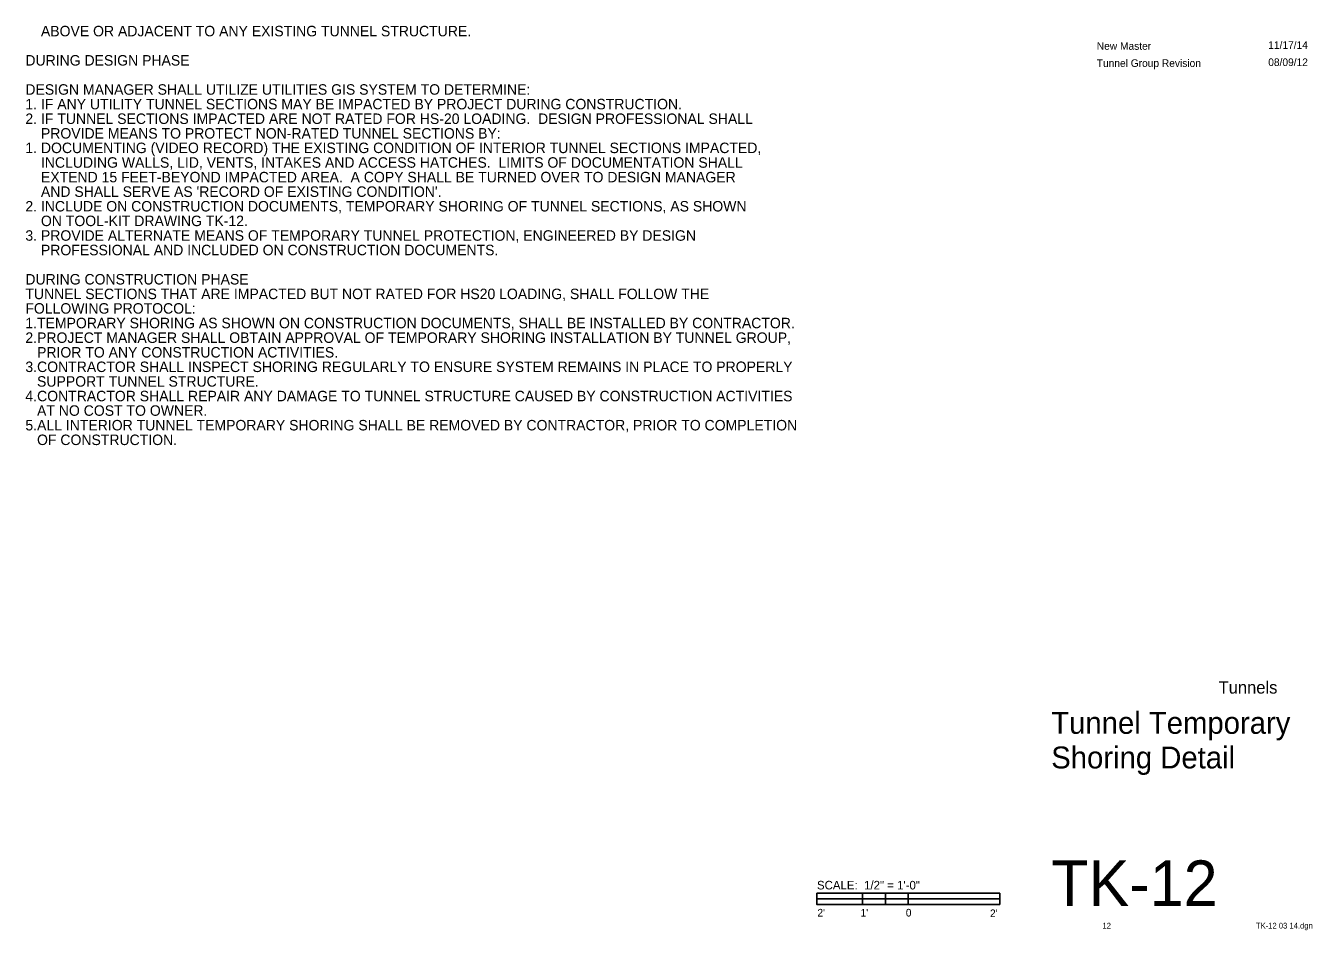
# Model space of a CAD drawing. Extents: x 10051 to 10282, y 10006 to 10178.
# Drawn here: x 10169.7 to 10282.4, y 10005.7 to 10084.8 of the extents above; entities that cross this region are included whole.
import ezdxf

# ---------------------------------------------------------------- set-up
doc = ezdxf.new("R2010")
doc.units = 0
for name, color, linetype in [('G-ANNO-CELL', 7, 'Continuous'), ('G-ANNO-TEXT', 7, 'Continuous'), ('G-DETL-LINE', 7, 'Continuous'), ('G-TITL-TEXT', 7, 'Continuous')]:
    doc.layers.add(name, color=color, linetype=linetype)

msp = doc.modelspace()

# ---------------------------------------------------------------- linework, layer by layer
at = {"layer": 'G-ANNO-CELL'}
for p, q in [((10238.99, 10008.91), (10246.99, 10008.91)), ((10238.99, 10008.91), (10238.99, 10007.91)), ((10242.99, 10008.91), (10242.99, 10007.91)), ((10246.99, 10008.91), (10254.99, 10008.91)), ((10246.99, 10008.91), (10246.99, 10007.91)), ((10254.99, 10008.91), (10254.99, 10007.91)), ((10238.99, 10008.41), (10242.99, 10008.41)), ((10238.99, 10007.91), (10246.99, 10007.91)), ((10242.99, 10008.41), (10246.99, 10008.41)), ((10246.99, 10008.41), (10254.99, 10008.41)), ((10246.99, 10007.91), (10254.99, 10007.91))]:
    msp.add_line(p, q, dxfattribs=at)
for points in [[(10242.99, 10008.41), (10244.99, 10008.41), (10244.99, 10008.91), (10242.99, 10008.91)], [(10246.99, 10008.91), (10254.99, 10008.91), (10254.99, 10008.41), (10246.99, 10008.41)], [(10238.99, 10008.41), (10242.99, 10008.41), (10242.99, 10007.91), (10238.99, 10007.91)], [(10244.99, 10007.91), (10246.99, 10007.91), (10246.99, 10008.41), (10244.99, 10008.41)]]:
    msp.add_lwpolyline(points, close=True, dxfattribs=at)

# ---------------------------------------------------------------- texts
for s, height, p in [('SCALE:  1/2" = 1\'-0"', 0.75, (10238.99, 10009.24)), ("2'", 0.667, (10239.03, 10006.87)), ("1'", 0.667, (10242.81, 10006.87)), ('0', 0.667, (10246.77, 10006.87)), ("2'", 0.667, (10254.14, 10006.82))]:
    msp.add_text(s, height=height, dxfattribs=at).set_placement(p)
at = {"layer": 'G-ANNO-TEXT'}
for s, p in [('    ABOVE OR ADJACENT TO ANY EXISTING TUNNEL STRUCTURE. ', (10169.69, 10083.9)), ('DURING DESIGN PHASE', (10169.69, 10081.34)), ('DESIGN MANAGER SHALL UTILIZE UTILITIES GIS SYSTEM TO DETERMINE:', (10169.69, 10078.79)), ('1. IF ANY UTILITY TUNNEL SECTIONS MAY BE IMPACTED BY PROJECT DURING CONSTRUCTION.', (10169.69, 10077.51)), ('2. IF TUNNEL SECTIONS IMPACTED ARE NOT RATED FOR HS-20 LOADING.  DESIGN PROFESSIONAL SHALL ', (10169.69, 10076.23)), ('    PROVIDE MEANS TO PROTECT NON-RATED TUNNEL SECTIONS BY:', (10169.69, 10074.95)), ('1. DOCUMENTING (VIDEO RECORD) THE EXISTING CONDITION OF INTERIOR TUNNEL SECTIONS IMPACTED, ', (10169.69, 10073.68)), ('    INCLUDING WALLS, LID, VENTS, INTAKES AND ACCESS HATCHES.  LIMITS OF DOCUMENTATION SHALL ', (10169.69, 10072.4)), ('    EXTEND 15 FEET-BEYOND IMPACTED AREA.  A COPY SHALL BE TURNED OVER TO DESIGN MANAGER ', (10169.69, 10071.12)), ("    AND SHALL SERVE AS 'RECORD OF EXISTING CONDITION'.", (10169.69, 10069.85)), ('2. INCLUDE ON CONSTRUCTION DOCUMENTS, TEMPORARY SHORING OF TUNNEL SECTIONS, AS SHOWN ', (10169.69, 10068.57)), ('    ON TOOL-KIT DRAWING TK-12.', (10169.69, 10067.29)), ('3. PROVIDE ALTERNATE MEANS OF TEMPORARY TUNNEL PROTECTION, ENGINEERED BY DESIGN ', (10169.69, 10066.01)), ('    PROFESSIONAL AND INCLUDED ON CONSTRUCTION DOCUMENTS.', (10169.69, 10064.74)), ('DURING CONSTRUCTION PHASE', (10169.69, 10062.18)), ('TUNNEL SECTIONS THAT ARE IMPACTED BUT NOT RATED FOR HS20 LOADING, SHALL FOLLOW THE ', (10169.69, 10060.9)), ('FOLLOWING PROTOCOL: ', (10169.69, 10059.63)), ('1.TEMPORARY SHORING AS SHOWN ON CONSTRUCTION DOCUMENTS, SHALL BE INSTALLED BY CONTRACTOR.', (10169.69, 10058.35)), ('2.PROJECT MANAGER SHALL OBTAIN APPROVAL OF TEMPORARY SHORING INSTALLATION BY TUNNEL GROUP, ', (10169.69, 10057.07)), ('   PRIOR TO ANY CONSTRUCTION ACTIVITIES.  ', (10169.69, 10055.79)), ('3.CONTRACTOR SHALL INSPECT SHORING REGULARLY TO ENSURE SYSTEM REMAINS IN PLACE TO PROPERLY ', (10169.69, 10054.52)), ('   SUPPORT TUNNEL STRUCTURE.  ', (10169.69, 10053.24)), ('4.CONTRACTOR SHALL REPAIR ANY DAMAGE TO TUNNEL STRUCTURE CAUSED BY CONSTRUCTION ACTIVITIES ', (10169.69, 10051.96)), ('   AT NO COST TO OWNER.', (10169.69, 10050.69)), ('5.ALL INTERIOR TUNNEL TEMPORARY SHORING SHALL BE REMOVED BY CONTRACTOR, PRIOR TO COMPLETION', (10169.69, 10049.41)), ('   OF CONSTRUCTION.', (10169.69, 10048.13))]:
    msp.add_text(s, height=0.9167, dxfattribs=at).set_placement(p)
at = {"layer": 'G-DETL-LINE'}
for s, height, p in [('New Master', 0.667, (10263.49, 10082.72)), ('11/17/14', 0.667, (10278.5, 10082.8)), ('Tunnel Group Revision', 0.6667, (10263.49, 10081.22)), ('08/09/12', 0.667, (10278.5, 10081.3))]:
    msp.add_text(s, height=height, dxfattribs=at).set_placement(p)
at = {"layer": 'G-TITL-TEXT'}
for s, height, p in [('Tunnels         ', 1.0833, (10274.15, 10026.38)), ('Tunnel Temporary     ', 1.9167, (10259.5, 10022.86)), ('Shoring Detail      ', 1.9167, (10259.5, 10019.83)), ('TK-12 ', 4, (10259.5, 10007.78)), ('12', 0.5, (10263.99, 10005.82)), ('TK-12 03 14.dgn', 0.5, (10277.42, 10005.82))]:
    msp.add_text(s, height=height, dxfattribs=at).set_placement(p)

doc.saveas('drawing.dxf')
